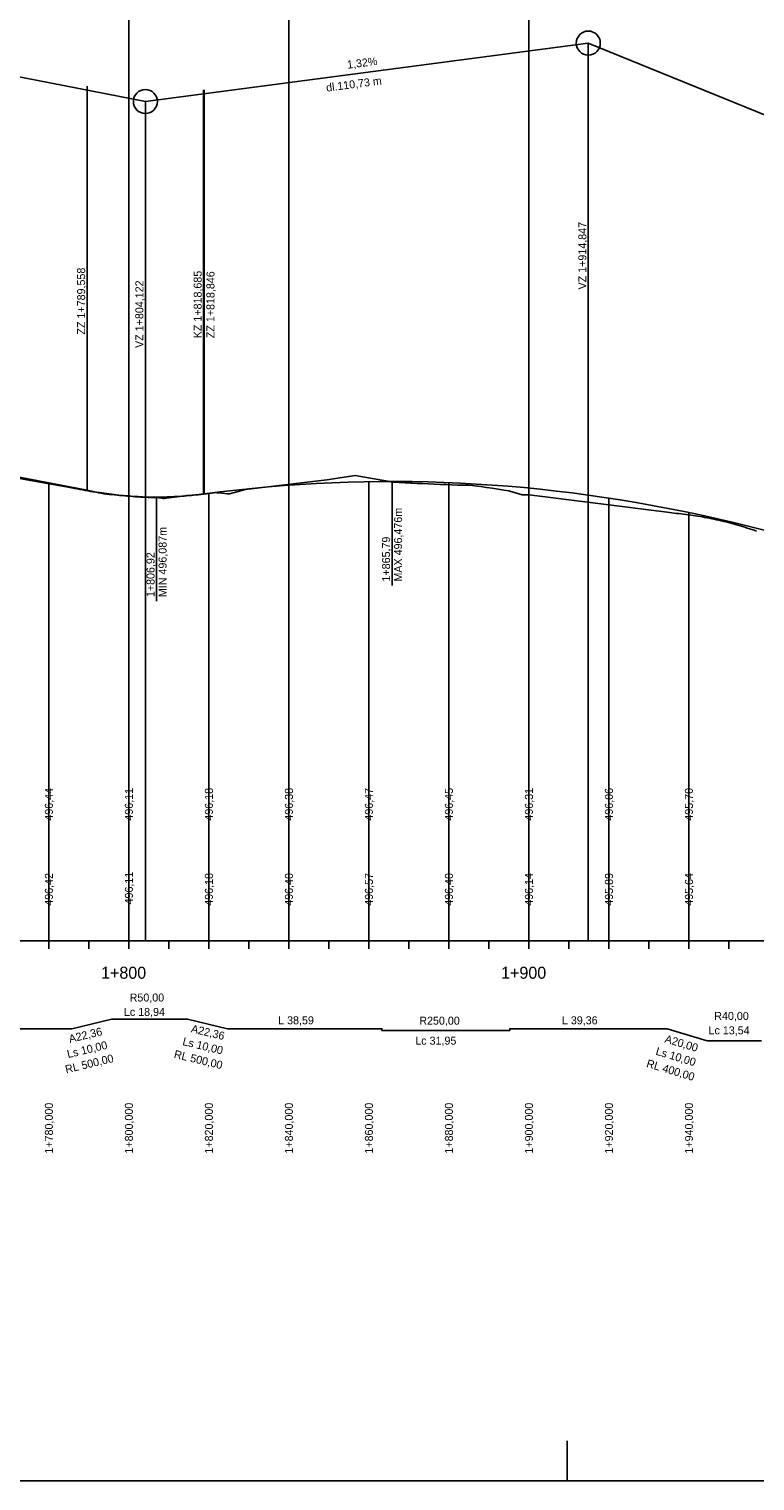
# Model space of a CAD drawing. Extents: x -632716 to -629545, y -1094726 to -1088285.
# Drawn here: x -630753.6 to -630572.1, y -1091981 to -1091618.1 of the extents above; entities that cross this region are included whole.
import ezdxf

# ---------------------------------------------------------------- set-up
doc = ezdxf.new("R2010")
doc.units = 0
for name, color, linetype in [('20', 7, 'Continuous'), ('Default', 7, 'Continuous'), ('formát', 7, 'Continuous'), ('NIVELETA_VYSKY', 7, 'Continuous'), ('REZ_POPIS', 7, 'Continuous'), ('REZ_TABULKA', 7, 'Continuous'), ('REZ_TENKA', 7, 'Continuous'), ('REZ_TLUSTA', 7, 'Continuous'), ('SKLONY_NIVELETA', 7, 'Continuous'), ('SKLONY_POPIS', 7, 'Continuous'), ('TECNY_NIVELETA', 7, 'Continuous'), ('TEREN_VYSKY', 7, 'Continuous'), ('VOZOVKA', 7, 'Continuous')]:
    doc.layers.add(name, color=color, linetype=linetype)

msp = doc.modelspace()

# ---------------------------------------------------------------- linework, layer by layer
at = {"layer": '20'}
for points in [[(-630748.64, -1091731.57), (-630748.64, -1091795.99), (-630748.64, -1091845.99), (-630748.64, -1091785.99)], [(-630688.64, -1091732.16), (-630688.64, -1091795.99), (-630688.64, -1091845.99), (-630688.64, -1091785.99)], [(-630668.64, -1091731.27), (-630668.64, -1091795.99), (-630668.64, -1091845.99), (-630668.64, -1091785.99)], [(-630648.64, -1091731.51), (-630648.64, -1091795.99), (-630648.64, -1091845.99), (-630648.64, -1091785.99)], [(-630728.64, -1091734.85), (-630728.64, -1091795.99), (-630728.64, -1091845.99), (-630728.64, -1091785.99)], [(-630708.64, -1091734.17), (-630708.64, -1091795.99), (-630708.64, -1091845.99), (-630708.64, -1091785.99)], [(-630628.64, -1091732.87), (-630628.64, -1091795.99), (-630628.64, -1091845.99), (-630628.64, -1091785.99)], [(-630608.64, -1091735.36), (-630608.64, -1091795.99), (-630608.64, -1091845.99), (-630608.64, -1091785.99)], [(-630588.64, -1091738.97), (-630588.64, -1091795.99), (-630588.64, -1091845.99), (-630588.64, -1091785.99)]]:
    msp.add_lwpolyline(points, dxfattribs=at)
at = {"layer": 'Default'}
for p, q in [((-630777.59, -1091725.93), (-630739.08, -1091733.43)), ((-630709.95, -1091734.35), (-630709.79, -1091734.32))]:
    msp.add_line(p, q, dxfattribs=at)
for points in [[(-630709.79, -1091734.32), (-630705.79, -1091733.82), (-630701.79, -1091733.36), (-630697.79, -1091732.94), (-630693.79, -1091732.57), (-630689.79, -1091732.25), (-630685.79, -1091731.97), (-630681.79, -1091731.73), (-630677.79, -1091731.54), (-630673.79, -1091731.39), (-630669.79, -1091731.29), (-630665.79, -1091731.24), (-630661.79, -1091731.23), (-630657.79, -1091731.26), (-630653.79, -1091731.34), (-630649.79, -1091731.47), (-630645.79, -1091731.63), (-630641.79, -1091731.85), (-630637.79, -1091732.11), (-630633.79, -1091732.41), (-630629.79, -1091732.76), (-630625.79, -1091733.16), (-630621.79, -1091733.6), (-630617.79, -1091734.08), (-630609.79, -1091735.19), (-630605.79, -1091735.8), (-630601.79, -1091736.47), (-630597.79, -1091737.18), (-630593.79, -1091737.93), (-630589.79, -1091738.73), (-630585.79, -1091739.58), (-630581.79, -1091740.47), (-630577.79, -1091741.4), (-630573.79, -1091742.38), (-630569.79, -1091743.41)], [(-630739.08, -1091733.43), (-630738.47, -1091733.55), (-630737.87, -1091733.66), (-630737.26, -1091733.77), (-630736.65, -1091733.87), (-630736.04, -1091733.97), (-630735.44, -1091734.07), (-630734.83, -1091734.16), (-630734.22, -1091734.25), (-630733.62, -1091734.33), (-630733.01, -1091734.41), (-630732.4, -1091734.48), (-630731.8, -1091734.55), (-630731.19, -1091734.62), (-630730.58, -1091734.68), (-630729.98, -1091734.74), (-630729.37, -1091734.79), (-630728.76, -1091734.84), (-630728.16, -1091734.89), (-630727.55, -1091734.93), (-630726.94, -1091734.97), (-630726.34, -1091735), (-630725.73, -1091735.03), (-630725.12, -1091735.06), (-630723.91, -1091735.1), (-630723.3, -1091735.11), (-630722.69, -1091735.12), (-630722.09, -1091735.12), (-630721.48, -1091735.12), (-630720.87, -1091735.12), (-630720.27, -1091735.11), (-630719.66, -1091735.1), (-630719.05, -1091735.08), (-630718.45, -1091735.06), (-630717.84, -1091735.04), (-630717.23, -1091735.01), (-630716.63, -1091734.98), (-630716.02, -1091734.94), (-630715.41, -1091734.9), (-630714.81, -1091734.85), (-630714.2, -1091734.81), (-630713.59, -1091734.75), (-630712.99, -1091734.69), (-630712.38, -1091734.63), (-630711.77, -1091734.57), (-630711.17, -1091734.5), (-630710.56, -1091734.42), (-630709.95, -1091734.35)]]:
    msp.add_lwpolyline(points, dxfattribs=at)
at = {"layer": 'formát'}
msp.add_line((-630619.11, -1091981.01), (-630619.11, -1091971.01), dxfattribs=at)
msp.add_lwpolyline([(-632628.81, -1091981.01), (-629779.11, -1091981.01), (-629779.11, -1091387.01), (-632628.81, -1091387.01)], close=True, dxfattribs=at)
at = {"layer": 'REZ_TABULKA'}
msp.add_lwpolyline([(-630783.7, -1091867.99), (-630742.92, -1091867.99), (-630742.92, -1091867.99), (-630732.92, -1091865.59), (-630732.92, -1091865.59), (-630713.98, -1091865.59), (-630713.98, -1091865.59), (-630703.98, -1091867.99), (-630703.98, -1091867.99), (-630665.39, -1091867.99), (-630665.39, -1091868.47), (-630633.44, -1091868.47), (-630633.44, -1091867.99), (-630594.07, -1091867.99), (-630594.07, -1091867.99), (-630584.07, -1091870.99), (-630584.07, -1091870.99), (-630570.53, -1091870.99)], dxfattribs=at)
at = {"layer": 'REZ_TENKA'}
for p, q in [((-630748.64, -1091847.99), (-630748.64, -1091845.99)), ((-630738.64, -1091847.99), (-630738.64, -1091845.99)), ((-630718.64, -1091847.99), (-630718.64, -1091845.99)), ((-630708.64, -1091847.99), (-630708.64, -1091845.99)), ((-630698.64, -1091847.99), (-630698.64, -1091845.99)), ((-630688.64, -1091847.99), (-630688.64, -1091845.99)), ((-630678.64, -1091847.99), (-630678.64, -1091845.99)), ((-630668.64, -1091847.99), (-630668.64, -1091845.99)), ((-630658.64, -1091847.99), (-630658.64, -1091845.99)), ((-630648.64, -1091847.99), (-630648.64, -1091845.99)), ((-630638.64, -1091847.99), (-630638.64, -1091845.99)), ((-630618.64, -1091847.99), (-630618.64, -1091845.99)), ((-630608.64, -1091847.99), (-630608.64, -1091845.99)), ((-630598.64, -1091847.99), (-630598.64, -1091845.99)), ((-630588.64, -1091847.99), (-630588.64, -1091845.99)), ((-630578.64, -1091847.99), (-630578.64, -1091845.99))]:
    msp.add_line(p, q, dxfattribs=at)
at = {"layer": 'REZ_TLUSTA'}
for p, q in [((-630728.64, -1091847.99), (-630728.64, -1091843.99)), ((-630628.64, -1091847.99), (-630628.64, -1091843.99)), ((-632528.64, -1091845.99), (-630208.64, -1091845.99))]:
    msp.add_line(p, q, dxfattribs=at)
at = {"layer": 'SKLONY_NIVELETA'}
for p, q in [((-630628.64, -1091573.48), (-630628.64, -1091732.87)), ((-630796.32, -1091622.28), (-630724.52, -1091636.27)), ((-630724.52, -1091636.27), (-630613.79, -1091621.65)), ((-630613.79, -1091621.65), (-630613.79, -1091845.99)), ((-630613.79, -1091621.65), (-630460.12, -1091684.35)), ((-630724.52, -1091636.27), (-630724.52, -1091845.99)), ((-630777.59, -1091725.93), (-630739.08, -1091733.43)), ((-630709.95, -1091734.35), (-630709.79, -1091734.32))]:
    msp.add_line(p, q, dxfattribs=at)
for points in [[(-630709.79, -1091734.32), (-630705.79, -1091733.82), (-630701.79, -1091733.36), (-630697.79, -1091732.94), (-630693.79, -1091732.57), (-630689.79, -1091732.25), (-630685.79, -1091731.97), (-630681.79, -1091731.73), (-630677.79, -1091731.54), (-630673.79, -1091731.39), (-630669.79, -1091731.29), (-630665.79, -1091731.24), (-630661.79, -1091731.23), (-630657.79, -1091731.26), (-630653.79, -1091731.34), (-630649.79, -1091731.47), (-630645.79, -1091731.63), (-630641.79, -1091731.85), (-630637.79, -1091732.11), (-630633.79, -1091732.41), (-630629.79, -1091732.76), (-630625.79, -1091733.16), (-630621.79, -1091733.6), (-630617.79, -1091734.08), (-630609.79, -1091735.19), (-630605.79, -1091735.8), (-630601.79, -1091736.47), (-630597.79, -1091737.18), (-630593.79, -1091737.93), (-630589.79, -1091738.73), (-630585.79, -1091739.58), (-630581.79, -1091740.47), (-630577.79, -1091741.4), (-630573.79, -1091742.38), (-630569.79, -1091743.41)], [(-630739.08, -1091733.43), (-630738.47, -1091733.55), (-630737.87, -1091733.66), (-630737.26, -1091733.77), (-630736.65, -1091733.87), (-630736.04, -1091733.97), (-630735.44, -1091734.07), (-630734.83, -1091734.16), (-630734.22, -1091734.25), (-630733.62, -1091734.33), (-630733.01, -1091734.41), (-630732.4, -1091734.48), (-630731.8, -1091734.55), (-630731.19, -1091734.62), (-630730.58, -1091734.68), (-630729.98, -1091734.74), (-630729.37, -1091734.79), (-630728.76, -1091734.84), (-630728.16, -1091734.89), (-630727.55, -1091734.93), (-630726.94, -1091734.97), (-630726.34, -1091735), (-630725.73, -1091735.03), (-630725.12, -1091735.06), (-630723.91, -1091735.1), (-630723.3, -1091735.11), (-630722.69, -1091735.12), (-630722.09, -1091735.12), (-630721.48, -1091735.12), (-630720.87, -1091735.12), (-630720.27, -1091735.11), (-630719.66, -1091735.1), (-630719.05, -1091735.08), (-630718.45, -1091735.06), (-630717.84, -1091735.04), (-630717.23, -1091735.01), (-630716.63, -1091734.98), (-630716.02, -1091734.94), (-630715.41, -1091734.9), (-630714.81, -1091734.85), (-630714.2, -1091734.81), (-630713.59, -1091734.75), (-630712.99, -1091734.69), (-630712.38, -1091734.63), (-630711.77, -1091734.57), (-630711.17, -1091734.5), (-630710.56, -1091734.42), (-630709.95, -1091734.35)]]:
    msp.add_lwpolyline(points, dxfattribs=at)
for centre in [(-630613.79, -1091621.65), (-630724.52, -1091636.27)]:
    msp.add_circle(centre, 3, dxfattribs=at)
at = {"layer": 'TECNY_NIVELETA'}
for p, q in [((-630728.64, -1091734.85), (-630728.64, -1091569.07)), ((-630688.64, -1091732.16), (-630688.64, -1091575.77)), ((-630613.79, -1091621.65), (-630613.79, -1091621.65)), ((-630739.08, -1091733.43), (-630739.08, -1091632.43)), ((-630709.95, -1091734.35), (-630709.95, -1091633.35)), ((-630709.79, -1091734.32), (-630709.79, -1091633.32)), ((-630724.52, -1091636.27), (-630724.52, -1091636.27)), ((-630662.85, -1091731.23), (-630662.85, -1091757.23)), ((-630721.72, -1091735.12), (-630721.72, -1091761.12))]:
    msp.add_line(p, q, dxfattribs=at)
at = {"layer": 'VOZOVKA'}
msp.add_lwpolyline([(-630756.02, -1091730.46), (-630752.73, -1091731.05), (-630742.92, -1091732.84), (-630742.25, -1091732.96), (-630741.59, -1091733.09), (-630740.92, -1091733.21), (-630740.25, -1091733.33), (-630739.59, -1091733.45), (-630738.92, -1091733.57), (-630738.25, -1091733.69), (-630737.59, -1091733.81), (-630736.92, -1091733.93), (-630736.25, -1091734.05), (-630735.59, -1091734.17), (-630734.92, -1091734.28), (-630734.65, -1091734.33), (-630734.25, -1091734.37), (-630733.59, -1091734.44), (-630732.92, -1091734.5), (-630732.27, -1091734.57), (-630731.61, -1091734.63), (-630730.96, -1091734.69), (-630730.31, -1091734.75), (-630729.65, -1091734.81), (-630729, -1091734.87), (-630728.35, -1091734.92), (-630727.7, -1091734.98), (-630727.04, -1091735.03), (-630726.73, -1091735.06), (-630726.39, -1091735.07), (-630725.74, -1091735.1), (-630725.08, -1091735.12), (-630724.43, -1091735.15), (-630723.78, -1091735.18), (-630723.12, -1091735.21), (-630722.47, -1091735.23), (-630721.82, -1091735.26), (-630721.76, -1091735.26), (-630721.17, -1091735.33), (-630720.51, -1091735.41), (-630720.04, -1091735.46), (-630719.86, -1091735.44), (-630719.21, -1091735.38), (-630718.55, -1091735.31), (-630717.9, -1091735.23), (-630717.25, -1091735.16), (-630716.59, -1091735.07), (-630715.94, -1091734.99), (-630715.29, -1091734.9), (-630714.64, -1091734.81), (-630714.12, -1091734.74), (-630713.98, -1091734.73), (-630713.32, -1091734.69), (-630712.89, -1091734.67), (-630712.65, -1091734.64), (-630711.98, -1091734.58), (-630711.32, -1091734.52), (-630710.65, -1091734.45), (-630709.98, -1091734.38), (-630709.32, -1091734.31), (-630709.27, -1091734.3), (-630708.65, -1091734.23), (-630707.98, -1091734.16), (-630707.32, -1091734.08), (-630706.69, -1091734.01), (-630706.65, -1091734.02), (-630705.98, -1091734.08), (-630705.32, -1091734.15), (-630704.65, -1091734.22), (-630703.98, -1091734.28), (-630703.53, -1091734.33), (-630699.52, -1091733.25), (-630679.19, -1091730.82), (-630672.07, -1091729.69), (-630665.39, -1091730.9), (-630663.94, -1091731.17), (-630662.78, -1091731.38), (-630662.49, -1091731.39), (-630661.04, -1091731.47), (-630659.58, -1091731.55), (-630658.13, -1091731.62), (-630657.91, -1091731.63), (-630656.68, -1091731.69), (-630655.23, -1091731.76), (-630653.77, -1091731.83), (-630652.32, -1091731.89), (-630650.87, -1091731.95), (-630649.42, -1091732.01), (-630647.96, -1091732.06), (-630646.51, -1091732.1), (-630645.06, -1091732.14), (-630643.61, -1091732.18), (-630642.75, -1091732.2), (-630642.15, -1091732.29), (-630640.7, -1091732.5), (-630639.25, -1091732.71), (-630637.8, -1091732.93), (-630636.34, -1091733.16), (-630634.89, -1091733.38), (-630633.68, -1091733.58), (-630633.44, -1091733.65), (-630630.3, -1091734.53), (-630628.57, -1091734.58), (-630594.07, -1091738.89), (-630593.49, -1091738.97), (-630592.9, -1091739.04), (-630592.31, -1091739.11), (-630591.72, -1091739.19), (-630591.13, -1091739.26), (-630590.55, -1091739.34), (-630589.96, -1091739.41), (-630589.37, -1091739.49), (-630588.78, -1091739.56), (-630588.19, -1091739.64), (-630587.6, -1091739.72), (-630587.02, -1091739.8), (-630586.47, -1091739.87), (-630586.43, -1091739.88), (-630585.84, -1091739.98), (-630585.25, -1091740.08), (-630584.66, -1091740.19), (-630584.07, -1091740.3), (-630583.49, -1091740.41), (-630582.9, -1091740.53), (-630582.31, -1091740.65), (-630581.72, -1091740.78), (-630581.52, -1091740.82), (-630581.13, -1091740.91), (-630580.54, -1091741.05), (-630579.95, -1091741.2), (-630579.36, -1091741.34), (-630578.78, -1091741.5), (-630578.19, -1091741.65), (-630577.6, -1091741.81), (-630577.01, -1091741.98), (-630576.42, -1091742.14), (-630575.83, -1091742.32), (-630575.24, -1091742.49), (-630574.65, -1091742.67), (-630574.07, -1091742.85), (-630573.48, -1091743.04), (-630572.89, -1091743.23), (-630572.3, -1091743.42), (-630571.71, -1091743.62)], dxfattribs=at)

# ---------------------------------------------------------------- texts
at = {"layer": 'NIVELETA_VYSKY'}
for s, p in [('496,44', (-630747.64, -1091815.99)), ('496,11', (-630727.64, -1091815.99)), ('496,18', (-630707.64, -1091815.99)), ('496,38', (-630687.64, -1091815.99)), ('496,47', (-630667.64, -1091815.99)), ('496,45', (-630647.64, -1091815.99)), ('496,31', (-630627.64, -1091815.99)), ('496,06', (-630607.64, -1091815.99)), ('495,70', (-630587.64, -1091815.99))]:
    msp.add_text(s, height=2, rotation=90, dxfattribs=at).set_placement(p)
at = {"layer": 'REZ_POPIS'}
for s, p in [('1+800', (-630735.59, -1091855.49)), ('1+900', (-630635.59, -1091855.49))]:
    msp.add_text(s, height=3, dxfattribs=at).set_placement(p)
at = {"layer": 'REZ_TABULKA'}
for s, p in [('R50,00', (-630728.45, -1091861.19)), ('Lc 18,94', (-630729.88, -1091864.79)), ('L 38,59', (-630691.32, -1091866.88)), ('R250,00', (-630656.04, -1091866.97)), ('L 39,36', (-630620.39, -1091866.88)), ('R40,00', (-630582.3, -1091865.79)), ('Lc 31,95', (-630657.04, -1091871.97)), ('Lc 13,54', (-630583.73, -1091869.39))]:
    msp.add_text(s, height=2, dxfattribs=at).set_placement(p)
for s, rotation, p in [('A22,36', 13.4957, (-630743.39, -1091871.53)), ('Ls 10,00', 346.5043, (-630715.37, -1091872.04)), ('A22,36', 346.5043, (-630713.24, -1091868.85)), ('A20,00', 343.3008, (-630594.84, -1091871.35)), ('Ls 10,00', 13.4957, (-630743.84, -1091875.34)), ('RL 500,00', 346.5043, (-630717.51, -1091875.23)), ('Ls 10,00', 343.3008, (-630597.1, -1091874.43)), ('RL 500,00', 13.4957, (-630744.3, -1091879.15)), ('RL 400,00', 343.3008, (-630599.42, -1091877.5)), ('1+780,000', 90, (-630747.64, -1091899.2)), ('1+800,000', 90, (-630727.64, -1091899.2)), ('1+820,000', 90, (-630707.64, -1091899.2)), ('1+840,000', 90, (-630687.64, -1091899.2)), ('1+860,000', 90, (-630667.64, -1091899.2)), ('1+880,000', 90, (-630647.64, -1091899.2)), ('1+900,000', 90, (-630627.64, -1091899.2)), ('1+920,000', 90, (-630607.64, -1091899.2)), ('1+940,000', 90, (-630587.64, -1091899.2))]:
    msp.add_text(s, height=2, rotation=rotation, dxfattribs=at).set_placement(p)
at = {"layer": 'SKLONY_POPIS'}
for s, rotation, p in [('1,32%', 7.5216, (-630673.95, -1091628.08)), ('dl.110,73 m', 7.5216, (-630679.19, -1091633.81)), ('VZ 1+914,847', 90, (-630614.29, -1091683.23)), ('ZZ 1+789,558', 90, (-630739.58, -1091694.51)), ('VZ 1+804,122', 90, (-630725.02, -1091697.85)), ('KZ 1+818,685', 90, (-630710.45, -1091695.43)), ('ZZ 1+818,846', 90, (-630707.25, -1091695.41)), ('MAX 496,476m', 90, (-630660.35, -1091756.23)), ('MIN 496,087m', 90, (-630719.22, -1091760.12)), ('1+865,79', 90, (-630663.35, -1091756.23)), ('1+806,92', 90, (-630722.22, -1091760.12))]:
    msp.add_text(s, height=2, rotation=rotation, dxfattribs=at).set_placement(p)
at = {"layer": 'TEREN_VYSKY'}
for s, p in [('496,42', (-630747.64, -1091837.25)), ('496,11', (-630727.64, -1091836.92)), ('496,18', (-630707.64, -1091837.25)), ('496,40', (-630687.64, -1091837.25)), ('496,57', (-630667.64, -1091837.25)), ('496,40', (-630647.64, -1091837.25)), ('496,14', (-630627.64, -1091837.25)), ('495,89', (-630607.64, -1091837.25)), ('495,64', (-630587.64, -1091837.25))]:
    msp.add_text(s, height=2, rotation=90, dxfattribs=at).set_placement(p)

doc.saveas('drawing.dxf')
